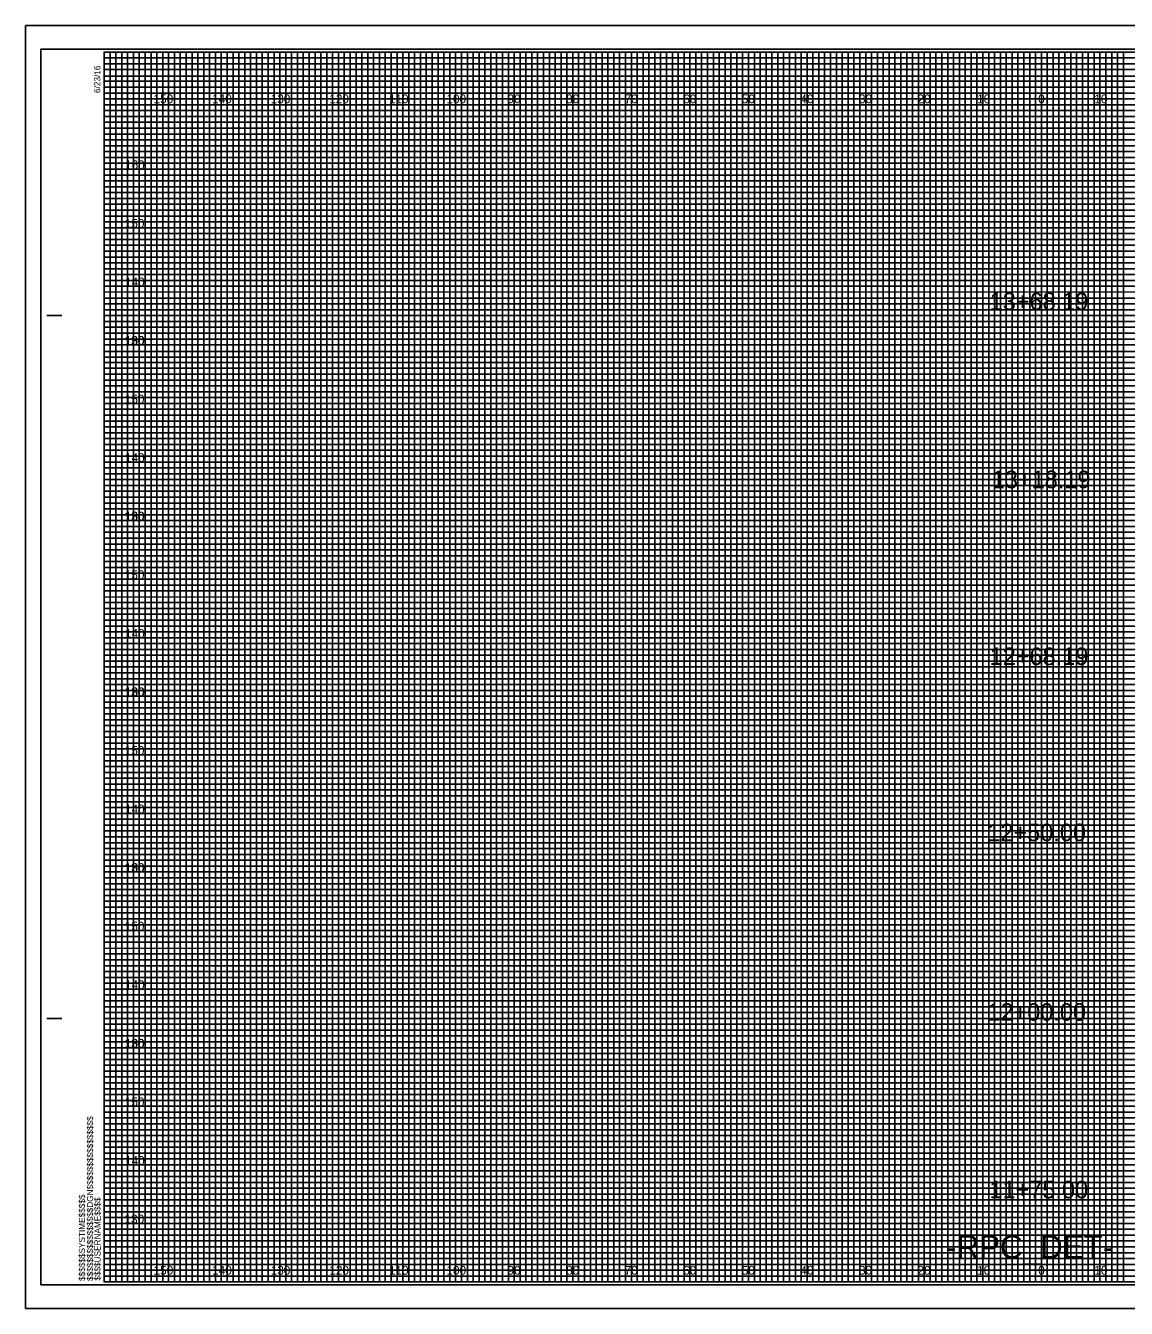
# Model space of a CAD drawing. Extents: x -13 to 323, y -5 to 654.
# Drawn here: x -13.4 to 174.5, y 215.5 to 434.5 of the extents above; entities that cross this region are included whole.
import ezdxf

# ---------------------------------------------------------------- set-up
doc = ezdxf.new("R2010")
doc.units = 0
for name, color, linetype in [('Exist Cross Section Cell', 7, 'Continuous'), ('Exist XS Center Line Elevation Label', 7, 'Continuous'), ('Exist XS Ground Line', 7, 'Continuous'), ('Prop CMT Pvmt Course 1', 7, 'Continuous'), ('Prop CMT Pvmt Course 2', 7, 'Continuous'), ('Prop CMT Pvmt Course 3', 7, 'Continuous'), ('Prop CMT Pvmt Surface', 7, 'Continuous'), ('Prop CMT Pvmt Surface Shoulder', 7, 'Continuous'), ('Prop CMT Shld Paved Course 1', 7, 'Continuous'), ('Prop CMT Shld Paved Course 2', 7, 'Continuous'), ('Prop CMT Shld Paved Course 3', 7, 'Continuous'), ('Prop CMT Slope Grass', 7, 'Continuous'), ('Prop XS Earthwork Shape', 7, 'Continuous')]:
    doc.layers.add(name, color=color, linetype=linetype)

msp = doc.modelspace()

# ---------------------------------------------------------------- linework, layer by layer
at = {"layer": 'Exist XS Center Line Elevation Label'}
for points in [[(0, 430), (5, 430), (5, 220), (15, 220), (15, 430), (25, 430), (25, 220), (35, 220), (35, 430), (45, 430), (45, 220), (55, 220), (55, 430), (65, 430), (65, 220), (75, 220), (75, 430), (85, 430), (85, 220), (95, 220), (95, 430), (105, 430), (105, 220), (115, 220), (115, 430), (125, 430), (125, 220), (135, 220), (135, 430), (145, 430), (145, 220), (155, 220), (155, 430), (165, 430), (165, 220), (175, 220)], [(0, 425), (275, 425)], [(0, 405), (320, 405), (320, 415), (0, 415)], [(0, 385), (320, 385), (320, 395), (0, 395)], [(0, 365), (320, 365), (320, 375), (0, 375)], [(0, 345), (320, 345), (320, 355), (0, 355)], [(0, 325), (320, 325), (320, 335), (0, 335)], [(0, 305), (320, 305), (320, 315), (0, 315)], [(0, 285), (320, 285), (320, 295), (0, 295)], [(0, 265), (320, 265), (320, 275), (0, 275)], [(0, 245), (320, 245), (320, 255), (0, 255)], [(0, 225), (320, 225), (320, 235), (0, 235)]]:
    msp.add_lwpolyline(points, dxfattribs=at)
at = {"layer": 'Exist XS Ground Line'}
for p, q in [((10, 430), (0, 430)), ((10, 220), (10, 430)), ((30, 430), (20, 430)), ((20, 430), (20, 220)), ((30, 220), (30, 430)), ((50, 430), (40, 430)), ((40, 430), (40, 220)), ((50, 220), (50, 430)), ((70, 430), (60, 430)), ((60, 430), (60, 220)), ((70, 220), (70, 430)), ((90, 430), (80, 430)), ((80, 430), (80, 220)), ((90, 220), (90, 430)), ((110, 430), (100, 430)), ((100, 430), (100, 220)), ((110, 220), (110, 430)), ((130, 430), (120, 430)), ((120, 430), (120, 220)), ((130, 220), (130, 430)), ((150, 430), (140, 430)), ((140, 430), (140, 220)), ((150, 220), (150, 430)), ((170, 430), (160, 430)), ((160, 430), (160, 220)), ((170, 220), (170, 430)), ((20, 220), (10, 220)), ((40, 220), (30, 220)), ((60, 220), (50, 220)), ((80, 220), (70, 220)), ((100, 220), (90, 220)), ((120, 220), (110, 220)), ((140, 220), (130, 220)), ((160, 220), (150, 220)), ((180, 220), (170, 220))]:
    msp.add_line(p, q, dxfattribs=at)
for points in [[(0, 420), (320, 420), (320, 410), (0, 410)], [(0, 400), (320, 400), (320, 390), (0, 390)], [(0, 380), (320, 380), (320, 370), (0, 370)], [(0, 360), (320, 360), (320, 350), (0, 350)], [(0, 340), (320, 340), (320, 330), (0, 330)], [(0, 320), (320, 320), (320, 310), (0, 310)], [(0, 300), (320, 300), (320, 290), (0, 290)], [(0, 280), (320, 280), (320, 270), (0, 270)], [(0, 260), (320, 260), (320, 250), (0, 250)], [(0, 240), (320, 240), (320, 230), (0, 230)]]:
    msp.add_lwpolyline(points, dxfattribs=at)
at = {"layer": 'Prop CMT Pvmt Course 1'}
for p, q in [((0, 429), (260, 429)), ((260, 427.98), (0, 427.98)), ((0, 427.98), (0, 427)), ((0, 427), (260, 427)), ((260, 425.89), (0, 425.89)), ((0, 425.89), (0, 424)), ((0, 424), (320, 424))]:
    msp.add_line(p, q, dxfattribs=at)
for points in [[(0, 423), (270, 423), (320, 423), (320, 422), (0, 422)], [(0, 421), (320, 421), (320, 419), (0, 419)], [(0, 418), (320, 418), (320, 417), (0, 416.98)], [(0, 416), (320, 416), (320, 414), (0, 414)], [(0, 413), (320, 413), (320, 412), (0, 412)], [(0, 411), (320, 411), (320, 409), (0, 409)], [(0, 408), (320, 408), (320, 407), (0, 407)], [(0, 406), (320, 406), (320, 404), (0, 404)], [(0, 403), (320, 403), (320, 402), (0, 402)], [(0, 401), (320, 401), (320, 399), (0, 399)], [(0, 398), (320, 398), (320, 397), (0, 397)], [(0, 396), (320, 396), (320, 393.95), (320, 393), (320, 392), (0, 392)], [(0, 394), (320, 394), (320, 393), (0, 393)], [(0, 391), (320, 391), (320, 389), (0, 389.03)], [(0, 389.03), (320, 389), (320, 388), (0, 388)], [(0, 387), (320, 387), (320, 386), (0, 386)], [(0, 384), (320, 384), (320, 383), (0, 383)], [(0, 382), (320, 382), (320, 381), (0, 381)], [(-0.07, 378.89), (320, 378.89), (320, 377.88), (-0.07, 377.88)], [(0, 377), (320, 377), (320, 376), (0, 376)], [(0, 374), (320, 374), (320, 373), (0, 373)], [(0, 372), (320, 372), (320, 371), (0, 371)], [(0, 369), (320, 369), (320, 368), (0, 368)], [(0, 367), (320, 367), (320, 366), (0, 366)], [(0, 364), (320, 364), (320, 363), (0, 363)], [(0, 362), (320, 362), (320, 361), (0, 361)], [(0, 359), (320, 359), (319.99, 357.98), (0, 358)], [(0, 357), (320, 357), (320, 356), (0, 356)], [(0, 354), (320, 354), (320, 353), (0, 353)], [(0, 352), (320, 352), (320, 351), (0, 351)], [(0, 349), (320, 349), (320, 348), (0, 348)], [(0, 347), (320, 347), (320, 346), (0, 346)], [(0, 344), (320, 344), (320, 343), (0, 343)], [(0, 342), (320, 342), (320, 341), (0, 341)], [(0, 339), (320, 339), (320, 338), (0, 338)], [(0, 336.99), (320.07, 336.91), (320, 336), (0, 336)], [(0, 334), (320, 334), (320, 333), (0, 333)], [(0, 332), (320, 332), (320, 331), (0, 331)], [(0, 329), (320, 329), (320, 328), (0, 328)], [(0, 327), (320, 327), (320, 326), (0, 326)], [(0, 324), (320, 324), (320, 323), (0, 323)], [(0, 322), (320, 322), (320, 321), (0, 321)], [(0, 319), (320, 319), (320, 318), (0, 318)], [(0, 317), (320, 317), (320, 316), (0, 316)], [(0, 314), (320, 314), (320, 313), (0, 313)], [(0, 312), (320, 312), (320, 311), (0, 311)], [(0, 309), (320, 309), (320, 308), (0, 308)], [(0, 307), (320, 307), (320, 306), (0, 306)], [(0, 304), (320, 304), (320, 303), (0, 303)], [(0, 302), (320, 302), (320, 301), (0, 301)], [(0, 299), (320, 299), (319.99, 297.98), (0, 298)], [(0, 297), (320, 297), (320, 296), (0, 296)], [(0, 294), (320, 294), (320, 293), (0, 293)], [(0, 292), (320, 292), (320, 291), (0, 291)], [(0, 289), (320, 289), (320, 288), (0, 288)], [(0, 287), (320, 287), (320, 286), (0, 286)], [(0, 284), (320, 284), (320, 283), (0, 283)], [(0, 282), (320, 282), (320, 281), (0, 281)], [(0, 279), (320, 279), (320, 278), (0, 278)], [(0, 276.99), (320.07, 276.91), (320, 276), (0, 276)], [(0, 274), (320, 274), (320, 273), (0, 273)], [(0, 272), (320, 272), (320, 271), (0, 271)], [(0, 269), (320, 269), (320, 268), (0, 268)], [(0, 267), (320, 267), (320, 266), (0, 266)], [(0, 264), (320, 264), (320, 263), (0, 263)], [(0, 262), (320, 262), (320, 261), (0, 261)], [(0, 259), (320, 259), (320, 258), (0, 258)], [(0, 257), (320, 257), (320, 256), (0, 256)], [(0, 254), (320, 254), (320, 253), (0, 253)], [(0, 252), (320, 252), (320, 251), (0, 251)], [(0, 249), (320, 249), (320, 248), (0, 248)], [(0, 247), (320, 247), (320, 246), (0, 246)], [(0, 244), (320, 244), (320, 243), (0, 243)], [(0, 242), (320, 242), (320, 241), (0, 241)], [(0, 239), (320, 239), (320, 238), (0, 238)], [(0, 237), (320, 237), (320, 236), (0, 236)], [(0, 234), (320, 234), (320, 233), (0, 233)], [(0, 232), (320, 232), (320, 231), (0, 231)], [(0, 229), (320, 229), (320, 228), (0, 228)], [(0, 227), (320, 227), (320, 226), (0, 226)], [(0, 224), (320, 224), (320, 223), (0, 223)], [(0, 222), (320, 222), (320, 221), (0, 221)]]:
    msp.add_lwpolyline(points, dxfattribs=at)
at = {"layer": 'Prop CMT Pvmt Surface'}
for points in [[(0, 220), (1, 220), (1, 430), (2, 430), (2, 220)], [(2, 220), (3, 220), (3, 430), (4, 430), (4, 220)], [(5, 220), (6, 220), (6, 430), (7, 430), (7, 220)], [(7, 220), (8, 220), (8, 430), (9, 430), (9, 220)], [(10, 220), (11, 220), (11, 430), (12, 430), (12, 220)], [(12, 220), (13, 220), (13, 430), (14, 430), (14, 220)], [(15, 220), (16, 220), (16, 430), (17, 430), (17, 220)], [(17, 220), (18, 220), (18, 430), (19, 430), (19, 220)], [(20, 220), (21, 220), (21, 430), (22, 430), (22, 220)], [(22, 220), (23, 220), (23, 430), (24, 430), (24, 220)], [(25, 220), (26, 220), (26, 430), (27, 430), (27, 220)], [(27, 220), (28, 220), (28, 430), (29, 430), (29, 220)], [(30, 220), (31, 220), (31, 430), (32, 430), (32, 220)], [(32, 220), (33, 220), (33, 430), (34, 430), (34, 220)], [(35, 220), (36, 220), (36, 430), (37, 430), (37, 220)], [(37, 220), (38, 220), (38, 430), (39, 430), (39, 220)], [(40, 220), (41, 220), (41, 430), (42, 430), (42, 220)], [(42, 220), (43, 220), (43, 430), (44, 430), (44, 220)], [(45, 220), (46, 220), (46, 430), (47, 430), (47, 220)], [(47, 220), (48, 220), (48, 430), (49, 430), (49, 220)], [(50, 220), (51, 220), (51, 430), (52, 430), (52, 220)], [(52, 220), (53, 220), (53, 430), (54, 430), (54, 220)], [(55, 220), (56, 220), (56, 430), (57, 430), (57, 220)], [(57, 220), (58, 220), (58, 430), (59, 430), (59, 220)], [(60, 220), (61, 220), (61, 430), (62, 430), (62, 220)], [(62, 220), (63, 220), (63, 430), (64, 430), (64, 220)], [(65, 220), (66, 220), (66, 430), (67, 430), (67, 220)], [(67, 220), (68, 220), (68, 430), (69, 430), (69, 220)], [(70, 220), (71, 220), (71, 430), (72, 430), (72, 220)], [(72, 220), (73, 220), (73, 430), (74, 430), (74, 220)], [(75, 220), (76, 220), (76, 430), (77, 430), (77, 220)], [(77, 220), (78, 220), (78, 430), (79, 430), (79, 220)], [(80, 220), (81, 220), (81, 430), (82, 430), (82, 220)], [(82, 220), (83, 220), (83, 430), (84, 430), (84, 220)], [(85, 220), (86, 220), (86, 430), (87, 430), (87, 220)], [(87, 220), (88, 220), (88, 430), (89, 430), (89, 220)], [(90, 220), (91, 220), (91, 430), (92, 430), (92, 220)], [(92, 220), (93, 220), (93, 430), (94, 430), (94, 220)], [(95, 220), (96, 220), (96, 430), (97, 430), (97, 220)], [(97, 220), (98, 220), (98, 430), (99, 430), (99, 220)], [(100, 220), (101, 220), (101, 430), (102, 430), (102, 220)], [(102, 220), (103, 220), (103, 430), (104, 430), (104, 220)], [(105, 220), (106, 220), (106, 430), (107, 430), (107, 220)], [(107, 220), (108, 220), (108, 430), (109, 430), (109, 220)], [(110, 220), (111, 220), (111, 430), (112, 430), (112, 220)], [(112, 220), (113, 220), (113, 430), (114, 430), (114, 220)], [(115, 220), (116, 220), (116, 430), (117, 430), (117, 220)], [(117, 220), (118, 220), (118, 430), (119, 430), (119, 220)], [(120, 220), (121, 220), (121, 430), (122, 430), (122, 220)], [(122, 220), (123, 220), (123, 430), (124, 430), (124, 220)], [(125, 220), (126, 220), (126, 430), (127, 430), (127, 220)], [(127, 220), (128, 220), (128, 430), (129, 430), (129, 220)], [(130, 220), (131, 220), (131, 430), (132, 430), (132, 220)], [(132, 220), (133, 220), (133, 430), (134, 430), (134, 220)], [(135, 220), (136, 220), (136, 430), (137, 430), (137, 220)], [(137, 220), (138, 220), (138, 430), (139, 430), (139, 220)], [(140, 220), (141, 220), (141, 430), (142, 430), (142, 220)], [(142, 220), (143, 220), (143, 430), (144, 430), (144, 220)], [(145, 220), (146, 220), (146, 430), (147, 430), (147, 220)], [(147, 220), (148, 220), (148, 430), (149, 430), (149, 220)], [(150, 220), (151, 220), (151, 430), (152, 430), (152, 220)], [(152, 220), (153, 220), (153, 430), (154, 430), (154, 220)], [(155, 220), (156, 220), (156, 430), (157, 430), (157, 220)], [(157, 220), (158, 220), (158, 430), (159, 430), (159, 220)], [(160, 220), (161, 220), (161, 430), (162, 430), (162, 220)], [(162, 220), (163, 220), (163, 430), (164, 430), (164, 220)], [(165, 220), (166, 220), (166, 430), (167, 430), (167, 220)], [(167, 220), (168, 220), (168, 430), (169, 430), (169, 220)], [(170, 220), (171, 220), (171, 430), (172, 430), (172, 220)], [(172, 220), (173, 220), (173, 430), (174, 430), (174, 220)]]:
    msp.add_lwpolyline(points, dxfattribs=at)
at = {"layer": 'Prop CMT Shld Paved Course 1'}
msp.add_lwpolyline([(-10.8, 219.5), (322.4, 219.5), (322.4, 430.5), (-10.8, 430.5)], close=True, dxfattribs=at)
at = {"layer": 'Prop CMT Shld Paved Course 2'}
for p, q in [((10, 220), (10, 430)), ((20, 220), (20, 430)), ((30, 220), (30, 430)), ((40, 220), (40, 430)), ((50, 220), (50, 430)), ((60, 220), (60, 430)), ((70, 220), (70, 430)), ((80, 220), (80, 430)), ((90, 220), (90, 430)), ((100, 220), (100, 430)), ((110, 220), (110, 430)), ((120, 220), (120, 430)), ((130, 220), (130, 430)), ((140, 220), (140, 430)), ((150, 220), (150, 430)), ((160, 220), (160, 430)), ((170, 220), (170, 430)), ((0, 420), (320, 420)), ((0, 410), (320, 410)), ((0, 400), (320, 400)), ((0, 390), (320, 390)), ((0, 380), (320, 380)), ((0, 370), (320, 370)), ((0, 360), (320, 360)), ((0, 350), (320, 350)), ((0, 340), (320, 340)), ((0, 330), (320, 330)), ((0, 320), (320, 320)), ((0, 310), (320, 310)), ((0, 300), (320, 300)), ((0, 290), (320, 290)), ((0, 280), (320, 280)), ((0, 270), (320, 270)), ((0, 260), (320, 260)), ((0, 250), (320, 250)), ((0, 240), (320, 240)), ((0, 230), (320, 230))]:
    msp.add_line(p, q, dxfattribs=at)
at = {"layer": 'Prop CMT Shld Paved Course 3'}
for p, q in [((323.3, 434.5), (-13.4, 434.5)), ((-13.4, 434.5), (-13.4, 215.5)), ((-13.4, 215.5), (323.3, 215.5))]:
    msp.add_line(p, q, dxfattribs=at)
at = {"layer": 'Prop CMT Slope Grass'}
for p, q in [((-9.8, 385), (-7.3, 385)), ((-9.7, 385), (-7.2, 385)), ((-9.8, 265), (-7.3, 265)), ((-9.7, 265), (-7.2, 265)), ((0, 220), (0, 220)), ((0, 220), (0, 220)), ((0, 220), (0, 220)), ((0, 220), (0, 220)), ((0, 220), (0, 220)), ((0, 220), (0, 220)), ((0, 220), (0, 220))]:
    msp.add_line(p, q, dxfattribs=at)
msp.add_lwpolyline([(320, 430), (0, 430), (0, 220), (320, 220)], close=True, dxfattribs=at)
at = {"layer": 'Prop XS Earthwork Shape'}
msp.add_lwpolyline([(-13.4, 215.5), (323.3, 215.5), (323.3, 434.5), (-13.4, 434.5)], close=True, dxfattribs=at)

# ---------------------------------------------------------------- texts
at = {"layer": 'Exist Cross Section Cell'}
for s, p in [('150', (8.44, 421.25)), ('140', (18.44, 421.25)), ('130', (28.44, 421.25)), ('120', (38.44, 421.25)), ('110', (48.62, 421.25)), ('100', (58.44, 421.25)), ('90', (68.86, 421.25)), ('80', (78.86, 421.25)), ('70', (88.86, 421.25)), ('60', (98.86, 421.25)), ('50', (108.86, 421.25)), ('40', (118.86, 421.25)), ('30', (128.86, 421.25)), ('20', (138.86, 421.25)), ('10', (149.04, 421.25)), ('0', (159.45, 421.25)), ('0', (159.45, 421.25)), ('10', (169.04, 421.25)), ('150', (8.44, 221.25)), ('140', (18.44, 221.25)), ('130', (28.44, 221.25)), ('120', (38.44, 221.25)), ('110', (48.62, 221.25)), ('100', (58.44, 221.25)), ('90', (68.86, 221.25)), ('80', (78.86, 221.25)), ('70', (88.86, 221.25)), ('60', (98.86, 221.25)), ('50', (108.86, 221.25)), ('40', (118.86, 221.25)), ('30', (128.86, 221.25)), ('20', (138.86, 221.25)), ('10', (149.04, 221.25)), ('0', (159.45, 221.25)), ('0', (159.45, 221.25)), ('10', (169.04, 221.25))]:
    msp.add_text(s, height=1.5, dxfattribs=at).set_placement(p)
at = {"layer": 'Prop CMT Pvmt Course 2'}
for s, p in [('160', (3.57, 410)), ('150', (3.52, 400)), ('140', (3.57, 390)), ('130', (3.49, 380)), ('160', (3.57, 380)), ('150', (3.52, 370)), ('140', (3.57, 360)), ('130', (3.49, 350)), ('160', (3.57, 350)), ('150', (3.52, 340)), ('140', (3.57, 330)), ('130', (3.49, 320)), ('160', (3.57, 320)), ('150', (3.52, 310)), ('140', (3.57, 300)), ('130', (3.49, 290)), ('160', (3.57, 290)), ('150', (3.52, 280)), ('140', (3.57, 270)), ('130', (3.49, 260)), ('160', (3.57, 260)), ('150', (3.52, 250)), ('140', (3.57, 240)), ('130', (3.49, 230))]:
    msp.add_text(s, height=1.5, dxfattribs=at).set_placement(p)
at = {"layer": 'Prop CMT Pvmt Course 3'}
for s, p in [('13+68.19', (151.17, 385.93)), ('13+18.19', (151.53, 355.52)), ('12+68.19', (151.17, 325.33)), ('12+50.00', (150.77, 295.25)), ('12+00.00', (150.77, 264.6)), ('11+75.00', (151.13, 234.28))]:
    msp.add_text(s, height=3, dxfattribs=at).set_placement(p)
at = {"layer": 'Prop CMT Pvmt Surface Shoulder'}
msp.add_text('-RPC_DET-', height=4, dxfattribs=at).set_placement((143.73, 224))
at = {"layer": 'Prop CMT Slope Grass'}
for s, p in [('6/23/16', (-0.65, 423)), ('$$$$$$$$$$$$$$$$DGN$$$$$$$$$$$$$$$$', (-1.88, 220.18)), ('$$$$$$SYSTIME$$$$$', (-3.26, 220.18)), ('$$$$USERNAME$$$$', (-0.62, 220.23))]:
    msp.add_text(s, height=1.05, rotation=90, dxfattribs=at).set_placement(p)

doc.saveas('drawing.dxf')
